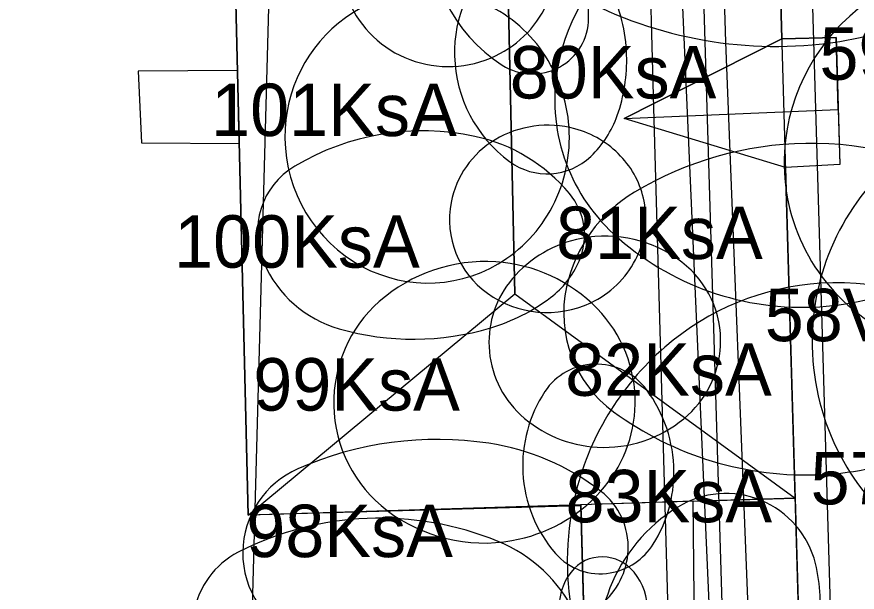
# Model space of a CAD drawing. Extents: x 738423 to 738903, y 6589762 to 6590172.
# Drawn here: x 738736.84 to 738760.87, y 6589912.78 to 6589929.25 of the extents above; entities that cross this region are included whole.
import ezdxf

# ---------------------------------------------------------------- set-up
doc = ezdxf.new("R2010")
doc.units = 0
for name, color, linetype in [('_1927_hoonestus', 7, 'Continuous'), ('_1927_katuse_kalded', 7, 'Continuous'), ('_1927_krundi_piir', 7, 'Continuous'), ('_ajalooline_kalmistu', 7, 'Continuous'), ('a_dendro_III_vk_puu', 7, 'Continuous'), ('a_dendro_IV_vk_puu', 7, 'Continuous'), ('a_dendro_puu_nr', 7, 'Continuous'), ('Default', 7, 'Continuous'), ('v_dp_jalak_liikumine', 7, 'Continuous'), ('v_olol_kitsendus_tehnov', 7, 'Continuous'), ('v_olol_transp_jjt_jalg', 7, 'Continuous'), ('v_olol_transp_tee', 7, 'Continuous')]:
    doc.layers.add(name, color=color, linetype=linetype)

# ---------------------------------------------------------------- blocks, each defined once
blk = doc.blocks.new('_U485')
at = {"layer": 'Default'}
for centre, radius, start, end in [((-0.0017445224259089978, 0.005065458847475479), 0.010929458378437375, 87.50427039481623, 148.33014341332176), ((-0.001763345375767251, 0.00463360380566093), 0.011361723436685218, 36.731167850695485, 87.50427039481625), ((-0.004409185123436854, 0.0026592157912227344), 0.014663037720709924, 352.3873186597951, 36.73116785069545), ((0.0013064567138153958, 0.003183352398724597), 0.014514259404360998, 148.3301434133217, 200.4469538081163), ((-0.003419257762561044, 0.0025269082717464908), 0.013664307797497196, 318.7914036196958, 352.3873186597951), ((0.00023824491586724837, 0.0027850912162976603), 0.0133742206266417, 200.4469538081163, 238.21319134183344), ((-0.0012924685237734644, 0.0006644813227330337), 0.01083731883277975, 280.91969827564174, 318.79140361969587), ((-0.0012410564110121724, 0.00039799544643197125), 0.010565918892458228, 238.21319134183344, 280.91969827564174)]:
    blk.add_arc(centre, radius, start, end, dxfattribs=at)
blk = doc.blocks.new('_U486')
at = {"layer": 'Default'}
for centre, radius, start, end in [((-0.0003131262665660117, 0.001286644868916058), 0.013928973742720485, 93.68563637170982, 147.00723376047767), ((-0.0003210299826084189, 0.0014093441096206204), 0.013806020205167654, 42.94427206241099, 93.68563637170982), ((0.0022463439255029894, 0.003798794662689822), 0.010298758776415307, 343.4602685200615, 42.944272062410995), ((-0.003335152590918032, 0.0032486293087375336), 0.010325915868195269, 147.00723376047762, 209.82543607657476), ((0.0010150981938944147, 0.004164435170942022), 0.011583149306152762, 307.5571722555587, 343.4602685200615), ((-0.002139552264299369, 0.003934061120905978), 0.01170405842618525, 209.82543607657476, 244.71560991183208), ((-0.000859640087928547, 0.006602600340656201), 0.014658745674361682, 275.7549600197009, 307.5571722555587), ((-0.0008630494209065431, 0.006636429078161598), 0.014692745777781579, 244.71560991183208, 275.7549600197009)]:
    blk.add_arc(centre, radius, start, end, dxfattribs=at)
blk = doc.blocks.new('_U507')
at = {"layer": 'Default'}
for centre, radius, start, end in [((0.0022359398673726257, 0.003019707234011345), 0.009530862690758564, 35.84665147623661, 109.64435277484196), ((0.002331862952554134, 0.0027509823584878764), 0.009816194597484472, 109.64435277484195, 176.69754633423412), ((0.0056890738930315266, 0.005514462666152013), 0.005270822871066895, 288.1678476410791, 35.846651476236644), ((-0.0030984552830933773, 0.0030643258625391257), 0.004376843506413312, 176.69754633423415, 288.31198269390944), ((0.004344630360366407, 0.009611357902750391), 0.009582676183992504, 265.9817138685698, 288.1678476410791), ((0.0030107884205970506, -0.009376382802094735), 0.009451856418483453, 85.98171386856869, 108.32281673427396), ((0.002905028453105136, -0.009057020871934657), 0.009115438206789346, 108.32281673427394, 114.27670833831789), ((-0.004576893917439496, 0.007531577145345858), 0.009082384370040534, 288.31198269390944, 294.27670833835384)]:
    blk.add_arc(centre, radius, start, end, dxfattribs=at)
blk = doc.blocks.new('_U508')
at = {"layer": 'Default'}
for centre, radius, start, end in [((-0.0036318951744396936, -0.0023381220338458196), 0.016520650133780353, 81.24880080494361, 131.5308812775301), ((-0.003578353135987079, -0.00199030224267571), 0.016168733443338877, 45.24796613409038, 81.24880080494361), ((-0.0045002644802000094, -0.001357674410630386), 0.015210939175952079, 131.53088127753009, 184.09120010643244), ((-0.002796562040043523, -0.0012017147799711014), 0.015058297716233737, 7.896067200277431, 45.24796613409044), ((-0.002746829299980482, -0.0011948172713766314), 0.01500808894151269, 327.04674772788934, 7.896067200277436), ((-0.0045406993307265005, -0.0013605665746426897), 0.015170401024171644, 184.0912001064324, 237.08728459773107), ((-0.0037136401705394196, -0.0005680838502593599), 0.016160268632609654, 287.74292772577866, 327.0467477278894), ((-0.0038175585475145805, -0.00024330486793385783), 0.016501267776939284, 237.08728459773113, 287.74292772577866)]:
    blk.add_arc(centre, radius, start, end, dxfattribs=at)
blk = doc.blocks.new('_U509')
at = {"layer": 'Default'}
for centre, radius, start, end in [((-0.002071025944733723, 0.006654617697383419), 0.0070059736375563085, 81.93680560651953, 147.9660456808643), ((-0.0022707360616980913, 0.0052448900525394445), 0.008429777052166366, 35.289743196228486, 81.93680560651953), ((0.0077378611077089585, 0.0005172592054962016), 0.018576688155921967, 147.96604568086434, 187.062808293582), ((-0.011382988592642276, -0.0012044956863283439), 0.019593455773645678, 5.185861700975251, 35.28974319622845), ((-0.011190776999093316, -0.0011870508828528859), 0.019400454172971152, 334.0583027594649, 5.185861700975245), ((0.007205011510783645, 0.0004512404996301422), 0.01803976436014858, 187.06280829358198, 223.94867704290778), ((-0.0010517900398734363, -0.006119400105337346), 0.00812538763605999, 285.0708979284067, 334.05830275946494), ((-0.0007549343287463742, -0.0072218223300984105), 0.006983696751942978, 223.94867704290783, 285.0708979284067)]:
    blk.add_arc(centre, radius, start, end, dxfattribs=at)
blk = doc.blocks.new('_U510')
at = {"layer": 'Default'}
for centre, radius, start, end in [((-0.002234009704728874, 0.003621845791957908), 0.010428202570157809, 83.85861024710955, 141.81307744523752), ((-0.0023261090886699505, 0.0027659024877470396), 0.011289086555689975, 40.26548763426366, 83.85861024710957), ((0.0021010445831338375, 0.00021209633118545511), 0.015943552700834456, 141.81307744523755, 187.9470157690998), ((-0.006220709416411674, -0.0005329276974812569), 0.016393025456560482, 4.371919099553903, 40.26548763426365), ((-0.006049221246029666, -0.0005198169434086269), 0.01622103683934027, 328.3116312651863, 4.371919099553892), ((0.0017957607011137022, 0.0001694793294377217), 0.015635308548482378, 187.9470157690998, 230.93314064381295), ((-0.0016978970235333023, -0.003206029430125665), 0.011107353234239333, 284.3815515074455, 328.3116312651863), ((-0.0015169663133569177, -0.003911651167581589), 0.010378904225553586, 230.9331406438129, 284.3815515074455)]:
    blk.add_arc(centre, radius, start, end, dxfattribs=at)
blk = doc.blocks.new('_U511')
at = {"layer": 'Default'}
for centre, radius, start, end in [((-0.001107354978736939, 0.008717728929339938), 0.009266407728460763, 91.92622742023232, 152.59534575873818), ((-0.001095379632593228, 0.008361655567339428), 0.009622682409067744, 36.571951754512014, 91.92622742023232), ((-0.012570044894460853, -0.00015147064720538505), 0.02391048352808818, 2.2970091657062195, 36.57195175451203), ((0.011826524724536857, 0.0020121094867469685), 0.02383522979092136, 152.59534575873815, 189.30545043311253), ((-0.010979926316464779, -8.768802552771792e-05), 0.022319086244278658, 328.9103543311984, 2.2970091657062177), ((0.00992344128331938, 0.0017002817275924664), 0.02190676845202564, 189.30545043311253, 222.43314613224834), ((0.0003663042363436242, -0.0069293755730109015), 0.009069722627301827, 275.344850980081, 328.91035433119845), ((0.0003755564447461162, -0.007028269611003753), 0.008970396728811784, 222.43314613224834, 275.344850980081)]:
    blk.add_arc(centre, radius, start, end, dxfattribs=at)
blk = doc.blocks.new('_U529')
at = {"layer": 'Default'}
for centre, radius, start, end in [((-0.0009507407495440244, -0.0008615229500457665), 0.008873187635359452, 88.17207562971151, 151.77694358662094), ((-0.0008742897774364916, 0.0015339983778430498), 0.006476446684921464, 25.999246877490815, 88.17207562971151), ((0.0022478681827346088, 0.003056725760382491), 0.003002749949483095, 287.37155704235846, 25.999246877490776), ((-0.005937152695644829, 0.0018147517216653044), 0.00321396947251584, 151.77694358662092, 274.0172751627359), ((-0.005564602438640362, 0.028029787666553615), 0.029169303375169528, 284.41277299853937, 287.37155704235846), ((-0.00739313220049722, 0.03514485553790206), 0.03651557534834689, 281.7683707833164, 284.4127729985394), ((-0.00824278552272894, 0.039223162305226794), 0.04068144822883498, 277.78296073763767, 281.7683707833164), ((-0.008904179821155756, 0.044062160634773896), 0.04556543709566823, 274.0172751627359, 277.78296073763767)]:
    blk.add_arc(centre, radius, start, end, dxfattribs=at)
blk = doc.blocks.new('_U530')
at = {"layer": 'Default'}
for centre, radius, start, end in [((0.00020160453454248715, -0.000885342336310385), 0.007735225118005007, 95.78125219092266, 147.95315372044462), ((0.00019364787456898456, -0.0008067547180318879), 0.007656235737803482, 46.39506916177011, 95.78125219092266), ((0.0030082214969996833, 0.0021483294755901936), 0.003575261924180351, 331.0231363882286, 46.39506916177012), ((-0.003284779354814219, 0.001297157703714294), 0.0036220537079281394, 147.9531537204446, 227.92365443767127), ((0.0011302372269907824, 0.003188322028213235), 0.005721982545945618, 300.0406639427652, 331.0231363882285), ((-0.0017090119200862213, 0.003042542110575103), 0.0059735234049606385, 227.92365443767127, 254.89526149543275), ((-0.0008049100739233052, 0.006534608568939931), 0.009587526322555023, 276.22499384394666, 300.0406639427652), ((-0.0007938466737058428, 0.006433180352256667), 0.009485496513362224, 254.8952614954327, 276.22499384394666)]:
    blk.add_arc(centre, radius, start, end, dxfattribs=at)
blk = doc.blocks.new('_U531')
at = {"layer": 'Default'}
for centre, radius, start, end in [((-0.0011824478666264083, 0.0018477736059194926), 0.0051957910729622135, 83.48141267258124, 148.64361776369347), ((-0.001199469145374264, 0.001698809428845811), 0.005345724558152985, 35.06840851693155, 83.48141267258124), ((-0.0006139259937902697, 0.0015013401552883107), 0.005861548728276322, 148.64361776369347, 209.57073882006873), ((-0.0016554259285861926, 0.0013787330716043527), 0.005902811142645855, 349.1346816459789, 35.06840851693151), ((-0.0014373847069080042, 0.0013368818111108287), 0.005680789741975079, 318.0268318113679, 349.1346816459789), ((-0.0008605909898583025, 0.001361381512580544), 0.005577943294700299, 209.5707388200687, 246.62903913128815), ((-0.0010710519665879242, 0.0010073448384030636), 0.00518804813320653, 285.43597539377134, 318.02683181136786), ((-0.0010486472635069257, 0.0009262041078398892), 0.005103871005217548, 246.62903913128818, 285.43597539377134)]:
    blk.add_arc(centre, radius, start, end, dxfattribs=at)
blk = doc.blocks.new('_U532')
at = {"layer": 'Default'}
for centre, radius, start, end in [((0.0002311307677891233, -0.00039516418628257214), 0.005652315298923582, 96.99671473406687, 141.50187310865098), ((0.00022733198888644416, -0.00036421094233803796), 0.005621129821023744, 53.95185444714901, 96.99671473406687), ((-0.0005356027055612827, -0.0014124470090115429), 0.006917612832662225, 15.328736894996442, 53.951854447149), ((0.001284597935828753, -0.0012330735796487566), 0.006998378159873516, 141.501873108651, 181.29568287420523), ((-0.0007833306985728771, -0.0014803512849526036), 0.00717447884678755, 326.657813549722, 15.328736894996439), ((0.001475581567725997, -0.0012287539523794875), 0.007189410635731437, 181.29568287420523, 223.80796263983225), ((0.000460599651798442, -0.002298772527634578), 0.005685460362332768, 271.50832866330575, 326.657813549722), ((0.00045812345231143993, -0.0022047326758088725), 0.00577953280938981, 223.80796263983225, 271.50832866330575)]:
    blk.add_arc(centre, radius, start, end, dxfattribs=at)
blk = doc.blocks.new('_U533')
at = {"layer": 'Default'}
for centre, radius, start, end in [((0.0006001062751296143, -0.0035595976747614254), 0.007639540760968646, 97.27465752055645, 135.34648364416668), ((0.0006117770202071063, -0.003651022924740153), 0.007731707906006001, 61.01745588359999, 97.27465752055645), ((0.002670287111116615, 6.529732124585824e-05), 0.003483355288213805, 5.782783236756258, 61.01745588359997), ((-0.0024238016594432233, -0.000572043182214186), 0.0033887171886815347, 135.34648364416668, 193.99081476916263), ((0.0025474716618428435, 5.28594671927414e-05), 0.003606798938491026, 310.9025056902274, 5.782783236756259), ((-0.002182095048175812, -0.000511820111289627), 0.003637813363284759, 193.9908147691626, 242.1863160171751), ((-0.00031037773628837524, 0.003351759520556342), 0.00797143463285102, 274.78715143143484, 310.9025056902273), ((-0.00028756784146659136, 0.0030793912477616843), 0.0076981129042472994, 242.186316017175, 274.78715143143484)]:
    blk.add_arc(centre, radius, start, end, dxfattribs=at)
blk = doc.blocks.new('_U534')
at = {"layer": 'Default'}
for centre, radius, start, end in [((0.00032315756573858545, -0.0007544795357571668), 0.0032282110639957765, 100.17419242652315, 147.53300546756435), ((0.0003344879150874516, -0.0008176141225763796), 0.0032923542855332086, 56.64981146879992, 100.17419242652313), ((0.0009196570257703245, 7.152245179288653e-05), 0.00222793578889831, 3.0724088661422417, 56.6498114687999), ((-0.0005577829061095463, -0.0001939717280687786), 0.002184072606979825, 147.53300546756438, 205.98706310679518), ((0.0007738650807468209, 6.36970533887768e-05), 0.0023739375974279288, 313.48710403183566, 3.072408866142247), ((-0.0003675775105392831, -0.00010125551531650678), 0.0023956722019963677, 205.98706310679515, 242.0445168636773), ((4.415659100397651e-05, 0.0008329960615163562), 0.0034342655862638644, 272.6785703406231, 313.48710403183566), ((5.0968495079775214e-05, 0.0006873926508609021), 0.003288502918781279, 242.04451686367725, 272.6785703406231)]:
    blk.add_arc(centre, radius, start, end, dxfattribs=at)
blk = doc.blocks.new('_U547')
at = {"layer": 'Default'}
for centre, radius, start, end in [((0.002327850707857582, 0.012856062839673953), 0.00476674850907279, 31.366537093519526, 138.98058165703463), ((0.008125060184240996, 0.007813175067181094), 0.01245039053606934, 138.98058165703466, 177.14331812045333), ((-0.008809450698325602, 0.006066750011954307), 0.017810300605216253, 342.01160273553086, 31.366537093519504), ((0.013719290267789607, 0.007534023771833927), 0.01805158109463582, 177.14331812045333, 208.64988950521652), ((4.1620773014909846e-05, 0.003192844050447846), 0.008504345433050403, 300.2461724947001, 342.01160273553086), ((0.007130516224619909, 0.00393426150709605), 0.010543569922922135, 208.6498895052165, 220.25108899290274), ((0.003951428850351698, 0.0012428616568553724), 0.006378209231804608, 220.2510889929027, 235.18367580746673), ((0.002443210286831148, -0.0009258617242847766), 0.003736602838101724, 235.18367580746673, 300.24617249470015)]:
    blk.add_arc(centre, radius, start, end, dxfattribs=at)
blk = doc.blocks.new('_U548')
at = {"layer": 'Default'}
for centre, radius, start, end in [((-0.0007984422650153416, 0.008774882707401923), 0.005225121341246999, 93.51041350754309, 163.3720066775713), ((-0.000795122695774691, 0.008720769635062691), 0.005279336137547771, 28.121308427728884, 93.51041350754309), ((-0.013553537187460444, 0.0019023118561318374), 0.019745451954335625, 355.6838438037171, 28.121308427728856), ((0.01321181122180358, 0.00459079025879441), 0.01984681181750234, 163.37200667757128, 197.54256395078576), ((-0.007684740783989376, 0.0014593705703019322), 0.013859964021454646, 326.657813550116, 355.6838438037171), ((0.0071611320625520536, 0.002678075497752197), 0.013501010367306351, 197.54256395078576, 223.80796263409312), ((0.0005087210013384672, -0.003931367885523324), 0.004052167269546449, 271.43577756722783, 326.6578135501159), ((0.0005031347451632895, -0.0037084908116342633), 0.004275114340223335, 223.80796263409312, 271.43577756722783)]:
    blk.add_arc(centre, radius, start, end, dxfattribs=at)
blk = doc.blocks.new('_U549')
at = {"layer": 'Default'}
for centre, radius, start, end in [((-2.52020025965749e-05, 0.0014992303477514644), 0.007739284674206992, 95.43202174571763, 147.11107946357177), ((-2.5960046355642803e-05, 0.0015072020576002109), 0.007731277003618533, 45.820017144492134, 95.43202174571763), ((-0.0010036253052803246, 0.0005011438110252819), 0.009134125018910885, 0.4099313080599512, 45.82001714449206), ((0.0011670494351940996, 0.0007282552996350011), 0.009159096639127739, 147.11107946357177, 194.34850127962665), ((-0.00081486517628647, 0.0005024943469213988), 0.008945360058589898, 318.6631581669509, 0.40993130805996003), ((0.0009448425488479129, 0.0006714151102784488), 0.00892973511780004, 194.34850127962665, 232.24430456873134), ((0.0001764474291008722, -0.0003695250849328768), 0.007625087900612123, 273.26143165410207, 318.663158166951), ((0.00017385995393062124, -0.00032411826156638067), 0.007670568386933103, 232.2443045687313, 273.26143165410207)]:
    blk.add_arc(centre, radius, start, end, dxfattribs=at)
blk = doc.blocks.new('_U550')
at = {"layer": 'Default'}
for centre, radius, start, end in [((0.0010768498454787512, 0.008115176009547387), 0.00438653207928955, 35.152532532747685, 117.78792620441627), ((0.0021725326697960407, 0.006035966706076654), 0.0067367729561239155, 117.78792620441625, 168.26576992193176), ((-0.0070003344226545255, 0.0024273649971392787), 0.014265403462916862, 352.2002239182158, 35.152532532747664), ((0.01061913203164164, 0.004281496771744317), 0.01536366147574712, 168.26576992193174, 201.0669252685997), ((-0.0024593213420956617, 0.0018053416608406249), 0.009681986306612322, 314.155959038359, 352.2002239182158), ((0.006411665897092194, 0.0026607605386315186), 0.010854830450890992, 201.0669252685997, 221.35099446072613), ((0.0021708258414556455, -0.0010716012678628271), 0.005205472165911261, 221.35099446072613, 250.812940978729), ((0.001686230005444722, -0.0024641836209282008), 0.0037309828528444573, 250.812940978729, 314.15595903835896)]:
    blk.add_arc(centre, radius, start, end, dxfattribs=at)
blk = doc.blocks.new('_U551')
at = {"layer": 'Default'}
for centre, radius, start, end in [((-0.0007368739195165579, 0.00274022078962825), 0.008459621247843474, 91.15951694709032, 151.91422385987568), ((-0.0007378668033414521, 0.0027892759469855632), 0.008410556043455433, 36.90792400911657, 91.15951694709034), ((-0.0003371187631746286, 0.003090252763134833), 0.007909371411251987, 340.81732358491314, 36.90792400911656), ((-0.0012117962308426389, 0.002993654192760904), 0.007921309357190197, 151.9142238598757, 214.92694244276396), ((-0.0005714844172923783, 0.0031717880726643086), 0.008157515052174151, 309.0899212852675, 340.81732358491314), ((-0.0009840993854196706, 0.0031526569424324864), 0.008199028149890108, 214.92694244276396, 246.9121132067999), ((-0.000829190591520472, 0.003489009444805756), 0.00856622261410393, 278.1480878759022, 309.08992128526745), ((-0.0008320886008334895, 0.0035092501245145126), 0.008586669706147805, 246.9121132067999, 278.1480878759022)]:
    blk.add_arc(centre, radius, start, end, dxfattribs=at)
blk = doc.blocks.new('_U552')
at = {"layer": 'Default'}
for centre, radius, start, end in [((0.0021467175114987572, 0.002038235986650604), 0.006042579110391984, 51.98442782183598, 117.27790325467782), ((0.0021865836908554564, 0.001960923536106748), 0.006129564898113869, 117.27790325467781, 163.81995302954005), ((0.0020192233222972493, 0.00187514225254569), 0.006249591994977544, 347.9129667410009, 51.984427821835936), ((0.0023239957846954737, 0.0019210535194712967), 0.006272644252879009, 163.81995302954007, 209.79729140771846), ((0.002100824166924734, 0.0018576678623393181), 0.006166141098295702, 300.24617249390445, 347.9129667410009), ((0.002265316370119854, 0.0018874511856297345), 0.006205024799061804, 209.79729140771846, 230.79204731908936), ((0.002194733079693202, 0.0018009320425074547), 0.006093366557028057, 230.79204731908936, 251.98049193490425), ((0.002172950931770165, 0.0017339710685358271), 0.006022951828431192, 251.98049193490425, 300.2461724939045)]:
    blk.add_arc(centre, radius, start, end, dxfattribs=at)

msp = doc.modelspace()

# ---------------------------------------------------------------- linework, layer by layer
at = {"layer": '_1927_hoonestus'}
for points in [[(738742.9119832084, 6589937.579054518), (738755.8497666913, 6589937.077773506), (738756.8029906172, 6589938.057600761), (738759.4850923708, 6589935.448320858), (738758.5480158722, 6589934.54201058), (738758.7178108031, 6589928.6132055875), (738760.266555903, 6589928.657560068), (738760.3706463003, 6589925.022989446), (738758.8231255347, 6589924.935884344), (738759.2916158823, 6589908.577398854), (738753.1586620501, 6589908.401757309), (738752.9623780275, 6589915.255493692), (738743.4516070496, 6589914.9831149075)], [(738743.1477720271, 6589927.705751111), (738740.3102095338, 6589927.693798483), (738740.4028276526, 6589925.64405944), (738743.1975086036, 6589925.623106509)]]:
    msp.add_lwpolyline(points, close=True, dxfattribs=at)
at = {"layer": '_1927_katuse_kalded'}
for points in [[(738743.4516070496, 6589914.9831149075), (738751.0753976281, 6589921.317903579), (738750.8823628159, 6589930.39873358), (738742.9119832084, 6589937.579054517)], [(738758.5480158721, 6589934.54201058), (738754.2550495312, 6589933.167425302), (738750.8823628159, 6589930.3987335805), (738751.0753976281, 6589921.31790358), (738759.0940977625, 6589915.47422674), (738758.8231255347, 6589924.935884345), (738754.2066055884, 6589926.336940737), (738758.7178108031, 6589928.6132055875)], [(738758.7178108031, 6589928.6132055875), (738754.2066055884, 6589926.336940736), (738760.3255573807, 6589926.59737927), (738760.266555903, 6589928.657560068)], [(738754.2066055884, 6589926.336940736), (738760.3255573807, 6589926.597379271), (738760.3706463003, 6589925.022989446), (738758.8231255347, 6589924.935884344)], [(738743.4516070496, 6589914.9831149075), (738751.0753976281, 6589921.317903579), (738759.0940977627, 6589915.47422674)], [(738756.2169037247, 6589911.730970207), (738756.1787003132, 6589915.382694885), (738752.9616277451, 6589915.281691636), (738753.1586620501, 6589908.401757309)], [(738759.2916158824, 6589908.577398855), (738756.2169037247, 6589911.730970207), (738756.1787003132, 6589915.382694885), (738759.0940977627, 6589915.474226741)]]:
    msp.add_lwpolyline(points, close=True, dxfattribs=at)
at = {"layer": '_1927_krundi_piir'}
msp.add_line((738759.9817993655, 6589884.477955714), (738758.4783109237, 6589936.975929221), dxfattribs=at)
at = {"layer": '_ajalooline_kalmistu'}
msp.add_lwpolyline([(738700.480405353, 6589884.053901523), (738711.8557000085, 6589939.5353000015), (738713.3969999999, 6589939.458000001), (738744.2612679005, 6589937.910991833), (738742.6678676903, 6589879.490577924)], close=True, dxfattribs=at)
at = {"layer": 'v_dp_jalak_liikumine'}
msp.add_lwpolyline([(738753.7352778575, 6590011.485218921), (738754.5485713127, 6589968.543440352), (738755.4664630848, 6589938.81512126), (738757.0489483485, 6589902.976712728), (738757.749514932, 6589889.633197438), (738760.3964895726, 6589885.01045508), (738760.6563499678, 6589876.988192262), (738761.0572489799, 6589862.973393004), (738761.3980093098, 6589851.105365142), (738761.7912117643, 6589844.0801351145)], dxfattribs=at)
at = {"layer": 'v_olol_kitsendus_tehnov'}
msp.add_lwpolyline([(738756.9105825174, 6589889.870097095), (738757.1525901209, 6589907.731297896), (738756.2368626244, 6589937.997240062), (738756.2034751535, 6589939.167527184)], dxfattribs=at)
at = {"layer": 'v_olol_transp_jjt_jalg'}
for points in [[(738753.3980000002, 6589984.476), (738754.3250000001, 6589953.163999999), (738755.04, 6589926.637), (738755.4860000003, 6589911.220000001), (738756.5250000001, 6589889.759999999), (738757.82206961, 6589886.935068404), (738757.3703897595, 6589885.530282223), (738754.0880000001, 6589882.902000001), (738752.2950952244, 6589882.167957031), (738745.265557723, 6589881.245987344), (738738.6560000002, 6589881.396000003), (738727.6409999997, 6589881.646000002), (738723.8518062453, 6589881.6181833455), (738723.8688999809, 6589879.598070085), (738727.889, 6589879.6620000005), (738739.6499999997, 6589879.9520000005), (738745.5079999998, 6589880.3), (738753.9679999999, 6589881.731000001), (738758.1444489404, 6589884.291527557), (738759.843, 6589884.707999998), (738760.6230000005, 6589848.891)], [(738762.2380000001, 6589844.465999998), (738761.5959999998, 6589867.022999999), (738760.9699535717, 6589884.81262032), (738760.8657554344, 6589887.773495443), (738759.372430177, 6589888.584165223), (738758.4950000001, 6589889.556), (738757.792, 6589911.368000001), (738757.1080000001, 6589928.520999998), (738756.3560000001, 6589953.211999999), (738755.3990000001, 6589984.343999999)]]:
    msp.add_lwpolyline(points, dxfattribs=at)
at = {"layer": 'v_olol_transp_tee'}
msp.add_lwpolyline([(738757.0262586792, 6590012.291021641), (738763.0496415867, 6590013.8166144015), (738763.91, 6589983.1489999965), (738764.929, 6589952.457999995), (738765.4810000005, 6589931.862999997), (738766.1660000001, 6589909.860999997), (738766.7020000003, 6589890.6209999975), (738767.8570000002, 6589856.707999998), (738768.121, 6589848.193999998), (738768.8037483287, 6589822.631606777), (738762.8293167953, 6589823.607741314), (738762.2380000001, 6589844.465999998), (738761.5959999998, 6589867.022999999), (738760.8119999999, 6589889.301), (738760.2139999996, 6589908.838999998), (738759.598, 6589929.524999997), (738758.8590000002, 6589952.364999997), (738757.8280000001, 6589984.569999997), (738757.361, 6590000.716999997)], close=True, dxfattribs=at)

# ---------------------------------------------------------------- block references
at = {"layer": 'a_dendro_III_vk_puu', "xscale": 500.0000000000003, "yscale": 500.0000000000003, "rotation": 85.69234851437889}
for name, p in [('_U511', (738759.1033105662, 6589934.344442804)), ('_U529', (738752.7103105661, 6589932.107442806)), ('_U552', (738750.0440000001, 6589929.727000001)), ('_U510', (738759.3223105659, 6589927.849442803)), ('_U530', (738752.772310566, 6589928.152442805)), ('_U485', (738766.8353105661, 6589925.752442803)), ('_U551', (738750.1259999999, 6589926.080999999)), ('_U486', (738767.198310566, 6589920.050442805)), ('_U550', (738749.9140000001, 6589922.248)), ('_U531', (738752.772310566, 6589923.965442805)), ('_U509', (738759.3743105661, 6589921.548442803)), ('_U532', (738752.9583105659, 6589919.831442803)), ('_U549', (738750.5159999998, 6589918.159)), ('_U508', (738759.809310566, 6589915.545442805)), ('_U533', (738753.3253105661, 6589916.233442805)), ('_U548', (738750.316, 6589913.966999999)), ('_U507', (738759.6533105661, 6589909.927442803)), ('_U547', (738750.577, 6589910.16))]:
    msp.add_blockref(name, p, dxfattribs=at)
at = {"layer": 'a_dendro_IV_vk_puu', "xscale": 500.0000000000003, "yscale": 500.0000000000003, "rotation": 85.69234851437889}
msp.add_blockref('_U534', (738753.5703105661, 6589912.218442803), dxfattribs=at)

# ---------------------------------------------------------------- texts
at = {"layer": 'a_dendro_puu_nr'}
for s, p in [('59Va', (738759.789874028, 6589927.443747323)), ('80KsA', (738750.9324658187, 6589926.90896179)), ('101KsA', (738742.3931525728, 6589925.834328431)), ('81KsA', (738752.2586880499, 6589922.315106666)), ('100KsA', (738741.3342069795, 6589922.067455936)), ('58Va', (738758.2263646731, 6589919.964410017)), ('82KsA', (738752.5170750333, 6589918.401860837)), ('99KsA', (738743.5979151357, 6589917.978455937)), ('57Va', (738759.5361130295, 6589915.294577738)), ('83KsA', (738752.526095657, 6589914.7834204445)), ('98KsA', (738743.3979151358, 6589913.786455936))]:
    msp.add_text(s, height=1.5, dxfattribs=at).set_placement(p)

doc.saveas('drawing.dxf')
